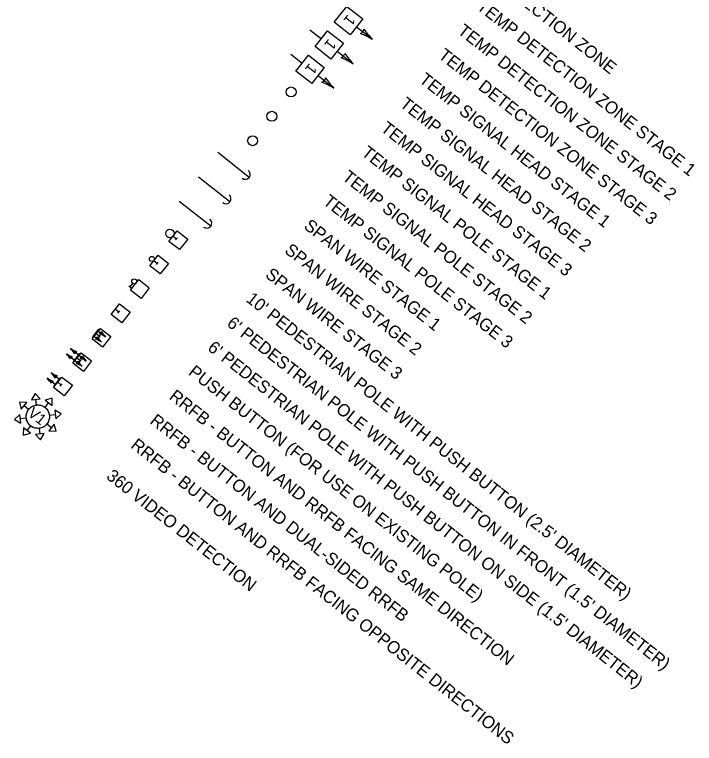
# Model space of a CAD drawing. Extents: x 999004 to 1000413, y 1985693 to 1986834.
# Drawn here: x 1000098.2 to 1000301.9, y 1986417.3 to 1986635.7 of the extents above; entities that cross this region are included whole.
import ezdxf

# ---------------------------------------------------------------- set-up
doc = ezdxf.new("R2010")
doc.units = 0
for name, color, linetype in [('DSN_RDWY_Alignment Annotation', 7, 'Continuous'), ('DSN_ROW_Line-Annotation', 7, 'Continuous'), ('DSN_ROW_Point', 7, 'Continuous'), ('EX_ALIGNMENT', 7, 'Continuous'), ('EX_ROW', 7, 'Continuous'), ('S_EDGE_PAVEMENT', 7, 'Continuous'), ('S_ORTHO_IMAGE', 7, 'Continuous'), ('S_PAVEMENT_CROWN', 7, 'Continuous'), ('S_SHOULDER', 7, 'Continuous'), ('S_SIDEWALK', 7, 'Continuous'), ('S_WALL_ANNOT', 7, 'Continuous')]:
    doc.layers.add(name, color=color, linetype=linetype)

msp = doc.modelspace()

# ---------------------------------------------------------------- linework, layer by layer
at = {"layer": 'DSN_RDWY_Alignment Annotation'}
for p, q in [((1000186.69, 1986631.17), (1000190.11, 1986628.48)), ((1000194.88, 1986624.75), (1000199.63, 1986621.01))]:
    msp.add_line(p, q, dxfattribs=at)
msp.add_lwpolyline([(1000188.24, 1986626.11), (1000191.99, 1986630.87), (1000196.75, 1986627.12), (1000193, 1986622.36)], close=True, dxfattribs=at)
for centre, radius, start, end in [((1000195.49, 1986624.27), 1.63, 289.9043, 353.599), ((1000221.13, 1986641.16), 29.47, 215.4052, 223.1433), ((1000185.05, 1986595.39), 29.47, 60.36, 68.0981)]:
    msp.add_arc(centre, radius, start, end, dxfattribs=at)
at = {"layer": 'DSN_ROW_Line-Annotation'}
msp.add_line((1000200.64, 1986632.05), (1000205.39, 1986628.31), dxfattribs=at)
msp.add_lwpolyline([(1000194, 1986633.41), (1000197.75, 1986638.18), (1000202.52, 1986634.42), (1000198.76, 1986629.66)], close=True, dxfattribs=at)
for centre, radius, start, end in [((1000201.25, 1986631.57), 1.63, 289.9043, 353.599), ((1000226.89, 1986648.46), 29.47, 215.4052, 223.1433), ((1000190.81, 1986602.69), 29.47, 60.36, 68.0981)]:
    msp.add_arc(centre, radius, start, end, dxfattribs=at)
at = {"layer": 'DSN_ROW_Point'}
for p, q in [((1000180.93, 1986623.87), (1000184.35, 1986621.18)), ((1000189.12, 1986617.45), (1000193.87, 1986613.71))]:
    msp.add_line(p, q, dxfattribs=at)
msp.add_lwpolyline([(1000182.48, 1986618.81), (1000186.23, 1986623.57), (1000190.99, 1986619.82), (1000187.24, 1986615.06)], close=True, dxfattribs=at)
for centre, radius, start, end in [((1000189.73, 1986616.97), 1.63, 289.9043, 353.599), ((1000179.29, 1986588.09), 29.47, 60.36, 68.0981), ((1000215.37, 1986633.86), 29.47, 215.4052, 223.1433)]:
    msp.add_arc(centre, radius, start, end, dxfattribs=at)
at = {"layer": 'EX_ALIGNMENT'}
msp.add_line((1000156.96, 1986572.32), (1000147.53, 1986579.75), dxfattribs=at)
msp.add_circle((1000169.52, 1986597.94), 1.5, dxfattribs=at)
msp.add_arc((1000155.78, 1986573.25), 1.5, 231.7516, 51.7516, dxfattribs=at)
at = {"layer": 'EX_ROW'}
msp.add_line((1000162.72, 1986579.62), (1000153.29, 1986587.05), dxfattribs=at)
msp.add_circle((1000175.28, 1986605.24), 1.5, dxfattribs=at)
msp.add_arc((1000161.54, 1986580.55), 1.5, 231.7516, 51.7516, dxfattribs=at)
at = {"layer": 'S_EDGE_PAVEMENT'}
for p, q in [((1000123.39, 1986541.48), (1000121.53, 1986539.12)), ((1000123.08, 1986541.08), (1000125.45, 1986539.21)), ((1000121.84, 1986539.51), (1000124.21, 1986537.64)), ((1000122.54, 1986540.4), (1000122.38, 1986540.2)), ((1000122.58, 1986540.05), (1000122.38, 1986540.2)), ((1000122.54, 1986540.4), (1000122.73, 1986540.24)), ((1000122.58, 1986540.05), (1000122.73, 1986540.24)), ((1000117.32, 1986533.78), (1000114.95, 1986535.65)), ((1000117.63, 1986534.18), (1000115.77, 1986531.82)), ((1000116.08, 1986532.21), (1000113.71, 1986534.08)), ((1000116.08, 1986532.21), (1000118.45, 1986530.34)), ((1000116.78, 1986533.1), (1000116.62, 1986532.9)), ((1000116.82, 1986532.74), (1000116.62, 1986532.9)), ((1000116.78, 1986533.1), (1000116.97, 1986532.94)), ((1000116.82, 1986532.74), (1000116.97, 1986532.94)), ((1000117.32, 1986533.78), (1000119.69, 1986531.91)), ((1000111.56, 1986526.48), (1000109.19, 1986528.35)), ((1000110.32, 1986524.91), (1000107.95, 1986526.78)), ((1000111.87, 1986526.87), (1000110.01, 1986524.52)), ((1000111.02, 1986525.79), (1000110.86, 1986525.6)), ((1000111.06, 1986525.44), (1000110.86, 1986525.6)), ((1000111.02, 1986525.79), (1000111.21, 1986525.64)), ((1000111.06, 1986525.44), (1000111.21, 1986525.64))]:
    msp.add_line(p, q, dxfattribs=at)
for centre, radius in [((1000181.04, 1986612.54), 1.5), ((1000144.72, 1986570.13), 1.25), ((1000139.35, 1986562.51), 0.75), ((1000134.05, 1986555.8), 0.75)]:
    msp.add_circle(centre, radius, dxfattribs=at)
for centre, radius, start, end in [((1000123.38, 1986540.84), 0.814, 289.9043, 353.599), ((1000136.2, 1986549.29), 14.74, 215.4052, 223.1433), ((1000122.15, 1986539.27), 0.814, 289.9043, 353.599), ((1000116.93, 1986524.84), 14.74, 60.36, 68.0981), ((1000134.97, 1986547.72), 14.74, 215.4052, 223.1433), ((1000118.16, 1986526.41), 14.74, 60.36, 68.0981), ((1000122.24, 1986548.46), 14.74, 240.36, 248.0981), ((1000104.2, 1986525.58), 14.74, 35.4052, 43.1433), ((1000117.02, 1986534.02), 0.814, 109.9043, 173.599), ((1000121, 1986546.89), 14.74, 240.36, 248.0981), ((1000102.96, 1986524.01), 14.74, 35.4052, 43.1433), ((1000115.78, 1986532.45), 0.814, 109.9043, 173.599), ((1000117.62, 1986533.54), 0.814, 289.9043, 353.599), ((1000112.4, 1986519.11), 14.74, 60.36, 68.0981), ((1000130.44, 1986541.99), 14.74, 215.4052, 223.1433), ((1000116.39, 1986531.97), 0.814, 289.9043, 353.599), ((1000111.17, 1986517.54), 14.74, 60.36, 68.0981), ((1000129.21, 1986540.42), 14.74, 215.4052, 223.1433), ((1000116.48, 1986541.16), 14.74, 240.36, 248.0981), ((1000098.44, 1986518.28), 14.74, 35.4052, 43.1433), ((1000115.24, 1986539.59), 14.74, 240.36, 248.0981), ((1000097.2, 1986516.7), 14.74, 35.4052, 43.1433), ((1000110.02, 1986525.15), 0.814, 109.9043, 173.599), ((1000111.26, 1986526.72), 0.814, 109.9043, 173.599)]:
    msp.add_arc(centre, radius, start, end, dxfattribs=at)
at = {"layer": 'S_ORTHO_IMAGE'}
msp.add_line((1000168.48, 1986586.92), (1000159.05, 1986594.35), dxfattribs=at)
msp.add_arc((1000167.3, 1986587.85), 1.5, 231.7516, 51.7516, dxfattribs=at)
at = {"layer": 'S_PAVEMENT_CROWN'}
for p, q in [((1000104.34, 1986522.21), (1000103.24, 1986520.31)), ((1000105.85, 1986520.62), (1000104.34, 1986522.21)), ((1000101.85, 1986519.53), (1000099.66, 1986519.59)), ((1000099.66, 1986519.59), (1000100.22, 1986517.47)), ((1000100.22, 1986517.47), (1000101.85, 1986519.53)), ((1000103.24, 1986520.31), (1000105.85, 1986520.62)), ((1000104.75, 1986518.73), (1000104.54, 1986520.47)), ((1000107.33, 1986518), (1000108.41, 1986519.38)), ((1000109.5, 1986520.76), (1000107.38, 1986520.19)), ((1000107.38, 1986520.19), (1000109.44, 1986518.56)), ((1000109.44, 1986518.56), (1000109.5, 1986520.76)), ((1000102.41, 1986517.42), (1000101.04, 1986518.5)), ((1000110.22, 1986517.17), (1000110.53, 1986514.57)), ((1000112.12, 1986516.08), (1000110.22, 1986517.17)), ((1000099.79, 1986515.94), (1000098.2, 1986514.43)), ((1000100.1, 1986513.33), (1000099.79, 1986515.94)), ((1000101.68, 1986514.84), (1000099.94, 1986514.64)), ((1000108.63, 1986515.66), (1000110.37, 1986515.87)), ((1000110.53, 1986514.57), (1000112.12, 1986516.08)), ((1000098.2, 1986514.43), (1000100.1, 1986513.33)), ((1000102.99, 1986512.51), (1000101.91, 1986511.13)), ((1000107.91, 1986513.09), (1000109.28, 1986512)), ((1000110.09, 1986513.03), (1000108.47, 1986510.97)), ((1000110.66, 1986510.91), (1000110.09, 1986513.03)), ((1000100.88, 1986511.94), (1000100.82, 1986509.75)), ((1000100.82, 1986509.75), (1000102.94, 1986510.32)), ((1000102.94, 1986510.32), (1000100.88, 1986511.94)), ((1000107.08, 1986510.19), (1000104.47, 1986509.88)), ((1000105.57, 1986511.78), (1000105.77, 1986510.04)), ((1000105.98, 1986508.29), (1000107.08, 1986510.19)), ((1000108.47, 1986510.97), (1000110.66, 1986510.91)), ((1000104.47, 1986509.88), (1000105.98, 1986508.29))]:
    msp.add_line(p, q, dxfattribs=at)
msp.add_lwpolyline([(1000104.45, 1986518.68), (1000104.75, 1986518.73), (1000105.05, 1986518.75), (1000105.35, 1986518.75), (1000105.66, 1986518.72), (1000105.96, 1986518.66), (1000106.25, 1986518.58), (1000106.54, 1986518.47), (1000106.81, 1986518.34), (1000107.08, 1986518.18), (1000107.32, 1986518), (1000107.55, 1986517.8), (1000107.77, 1986517.59), (1000107.96, 1986517.35), (1000108.13, 1986517.1), (1000108.28, 1986516.83), (1000108.41, 1986516.55), (1000108.51, 1986516.26), (1000108.58, 1986515.97), (1000108.63, 1986515.66), (1000108.66, 1986515.36), (1000108.65, 1986515.05), (1000108.62, 1986514.75), (1000108.57, 1986514.45), (1000108.48, 1986514.16), (1000108.37, 1986513.87), (1000108.24, 1986513.6), (1000108.09, 1986513.33), (1000107.91, 1986513.08), (1000107.71, 1986512.85), (1000107.49, 1986512.64), (1000107.25, 1986512.45), (1000107, 1986512.28), (1000106.73, 1986512.13), (1000106.46, 1986512), (1000106.17, 1986511.9), (1000105.87, 1986511.82), (1000105.57, 1986511.78), (1000105.27, 1986511.75), (1000105.27, 1986511.75), (1000104.96, 1986511.76), (1000104.66, 1986511.79), (1000104.36, 1986511.84), (1000104.06, 1986511.93), (1000103.78, 1986512.04), (1000103.5, 1986512.17), (1000103.24, 1986512.32), (1000102.99, 1986512.5), (1000102.76, 1986512.7), (1000102.55, 1986512.92), (1000102.35, 1986513.16), (1000102.18, 1986513.41), (1000102.03, 1986513.68), (1000101.91, 1986513.95), (1000101.81, 1986514.24), (1000101.73, 1986514.54), (1000101.68, 1986514.84), (1000101.66, 1986515.14), (1000101.66, 1986515.45), (1000101.7, 1986515.75), (1000101.75, 1986516.05), (1000101.84, 1986516.35), (1000101.94, 1986516.63), (1000102.08, 1986516.91), (1000102.23, 1986517.17), (1000102.41, 1986517.42), (1000102.61, 1986517.65), (1000102.83, 1986517.86), (1000103.06, 1986518.06), (1000103.32, 1986518.23), (1000103.58, 1986518.38), (1000103.86, 1986518.5), (1000104.15, 1986518.6)], close=True, dxfattribs=at)
msp.add_circle((1000105.16, 1986515.25), 3.5, dxfattribs=at)
at = {"layer": 'S_SHOULDER'}
for points in [[(1000146.94, 1986570.92), (1000150.08, 1986568.44), (1000147.6, 1986565.3), (1000144.46, 1986567.78)], [(1000141.18, 1986563.62), (1000144.32, 1986561.14), (1000141.84, 1986558), (1000138.7, 1986560.48)], [(1000135.42, 1986556.32), (1000138.56, 1986553.84), (1000136.08, 1986550.7), (1000132.94, 1986553.18)], [(1000129.66, 1986549.02), (1000132.8, 1986546.54), (1000130.32, 1986543.4), (1000127.18, 1986545.87)], [(1000123.9, 1986541.71), (1000127.04, 1986539.24), (1000124.56, 1986536.1), (1000121.42, 1986538.57)], [(1000118.14, 1986534.41), (1000121.28, 1986531.94), (1000118.8, 1986528.8), (1000115.66, 1986531.27)], [(1000112.37, 1986527.11), (1000115.52, 1986524.64), (1000113.04, 1986521.49), (1000109.9, 1986523.97)]]:
    msp.add_lwpolyline(points, close=True, dxfattribs=at)
at = {"layer": 'S_SIDEWALK'}
for p, q in [((1000145.7, 1986569.35), (1000146.73, 1986568.53)), ((1000146.46, 1986568.19), (1000147.01, 1986568.88)), ((1000139.94, 1986562.05), (1000140.97, 1986561.23)), ((1000140.7, 1986560.89), (1000141.24, 1986561.57)), ((1000132.43, 1986554.45), (1000133.12, 1986553.9)), ((1000133.59, 1986555.21), (1000132.77, 1986554.18)), ((1000128.42, 1986547.45), (1000129.45, 1986546.63)), ((1000129.18, 1986546.29), (1000129.72, 1986546.97)), ((1000122.66, 1986540.14), (1000123.69, 1986539.33)), ((1000123.42, 1986538.99), (1000123.96, 1986539.67)), ((1000116.9, 1986532.84), (1000117.93, 1986532.03)), ((1000117.66, 1986531.68), (1000118.2, 1986532.37)), ((1000111.14, 1986525.54), (1000112.17, 1986524.73)), ((1000111.9, 1986524.38), (1000112.44, 1986525.07))]:
    msp.add_line(p, q, dxfattribs=at)

# ---------------------------------------------------------------- texts
at = {"layer": 'DSN_RDWY_Alignment Annotation'}
msp.add_text('1', height=3.25, rotation=231.7516, dxfattribs=at).set_placement((1000192.32, 1986628.63))
at = {"layer": 'DSN_ROW_Line-Annotation'}
msp.add_text('1', height=3.25, rotation=231.7516, dxfattribs=at).set_placement((1000198.08, 1986635.93))
at = {"layer": 'DSN_ROW_Point'}
msp.add_text('1', height=3.25, rotation=231.7516, dxfattribs=at).set_placement((1000186.56, 1986621.32))
at = {"layer": 'S_PAVEMENT_CROWN'}
msp.add_text('V1', height=3.25, rotation=321.7516, dxfattribs=at).set_placement((1000101.91, 1986515.79))
at = {"layer": 'S_WALL_ANNOT'}
for s, p in [('DETECTION ZONE', (1000242.18, 1986644.88)), ('TEMP DETECTION ZONE STAGE 1', (1000236.42, 1986637.58)), ('TEMP DETECTION ZONE STAGE 2', (1000230.66, 1986630.28)), ('TEMP DETECTION ZONE STAGE 3', (1000224.9, 1986622.98)), ('TEMP SIGNAL HEAD STAGE 1', (1000219.14, 1986615.68)), ('TEMP SIGNAL HEAD STAGE 2', (1000213.38, 1986608.38)), ('TEMP SIGNAL HEAD STAGE 3', (1000207.62, 1986601.08)), ('TEMP SIGNAL POLE STAGE 1', (1000201.86, 1986593.78)), ('TEMP SIGNAL POLE STAGE 2', (1000196.1, 1986586.48)), ('TEMP SIGNAL POLE STAGE 3', (1000190.34, 1986579.17)), ('SPAN WIRE STAGE 1', (1000184.58, 1986571.87)), ('SPAN WIRE STAGE 2', (1000178.82, 1986564.57)), ('SPAN WIRE STAGE 3', (1000173.05, 1986557.27)), ("10' PEDESTRIAN POLE WITH PUSH BUTTON (2.5' DIAMETER)", (1000167.29, 1986549.97)), ("6' PEDESTRIAN POLE WITH PUSH BUTTON IN FRONT (1.5' DIAMETER)", (1000161.53, 1986542.67)), ("6' PEDESTRIAN POLE WITH PUSH BUTTON ON SIDE (1.5' DIAMETER)", (1000155.77, 1986535.37)), ('PUSH BUTTON (FOR USE ON EXISTING POLE)', (1000150.01, 1986528.07)), ('RRFB - BUTTON AND RRFB FACING SAME DIRECTION', (1000144.25, 1986520.77)), ('RRFB - BUTTON AND DUAL-SIDED RRFB', (1000138.49, 1986513.46)), ('RRFB - BUTTON AND RRFB FACING OPPOSITE DIRECTIONS', (1000132.73, 1986506.16)), ('360 VIDEO DETECTION', (1000125.42, 1986496.9))]:
    msp.add_text(s, height=3.72, rotation=321.7265, dxfattribs=at).set_placement(p)

doc.saveas('drawing.dxf')
